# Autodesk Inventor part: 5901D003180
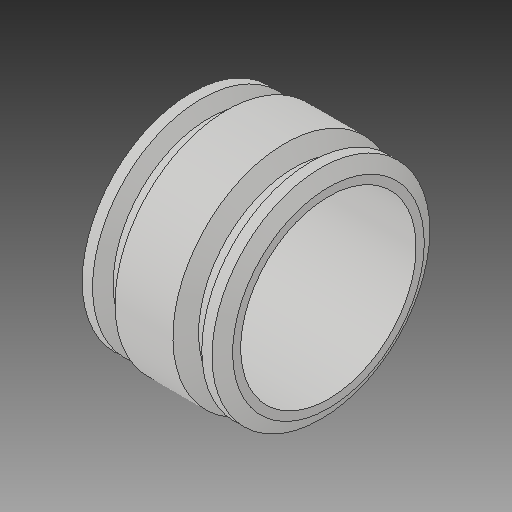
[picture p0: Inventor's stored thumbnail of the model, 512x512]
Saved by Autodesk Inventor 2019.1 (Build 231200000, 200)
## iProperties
Created: 2017-06
Part Number: 5901D003180
Material: Generic
Description: PLASSON COUPLER 18''DIPS
Document SubType Name: Modeling
Designer: KIM
Mass: 96874 g
Surface Area: 34549.7 cm^2
Volume: 96874 cm^3
Density: 1 g/cm^3
Appearance: Default
Author: KIM
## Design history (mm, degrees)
derived "5901D.ipt"
feature "Solid1::5901D.ipt"
tag "TaggingFeature1"
body "Solid1"
other parameters: "d13" = 375.92, "d15" = 187.96, "d16" = 187.96, "d17" = 455.1, "d22" = 564.896, "d23" = 581.406, "d24" = 497.10848, "d25" = 150 deg, "d26" = 150.368, "d27" = 120 deg, "d29" = 282.448, "d35" = 15, "d39" = 0, "d40" = 4, "d41" = 14, "d42" = 0, "d44" = 65.786, "d45" = 455.1, "d47" = 0, "d48" = 271.15008, "d49" = 65.786, "d50" = 60 deg, "d57" = 65.786, "d58" = 65.786, "d62" = 455.1, "d65" = 282.448, "d67" = 30 deg, "d68" = 120 deg, "d69" = 120 deg, "d70" = 120 deg, "d71" = 120 deg, "d72" = 120 deg, "d73" = 581.406, "d76" = 150.368, "d77" = 497.10848, "d_" = 455.1, "L_" = 375.92, "L_1" = 187.96, "D_" = 581.406, "A_" = 282.448, "A_1" = 25.4, "d60" = 187.96
